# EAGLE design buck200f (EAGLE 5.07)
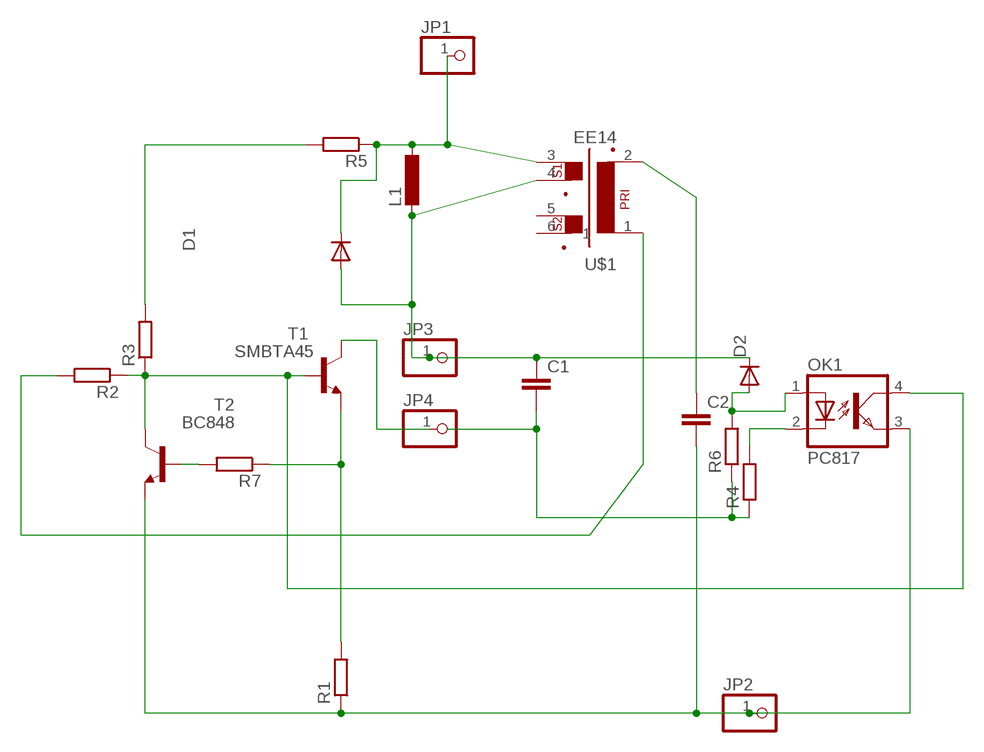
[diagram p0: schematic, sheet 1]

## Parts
C1  C-EU025-025X050  [C025-025X050]
C2  C-EUC0805  [C0805]
D1  DIODE-SMA-DO214  [SMA-DO214AC]
D2  DIODE-MINIMELF  [MINIMELF]
JP1  PINHD-1X11MM6  [1X1MM8]
JP2  PINHD-1X11MM6  [1X1MM8]
JP3  PINHD-1X11MM6  [1X1MM8]
JP4  PINHD-1X11MM6  [1X1MM8]
L1  L-EU0204/5  [0204/5]
OK1  PC817  [DIL04]
R1  R-EU_R0805  [R0805]
R2  R-EU_R0805  [R0805]
R3  R-EU_R1206  [R1206]
R4  R-EU_R0805  [R0805]
R5  R-EU_R1206  [R1206]
R6  R-EU_R0805  [R0805]
R7  R-EU_R0805  [R0805]
T1  SMBTA45  BC848  [SOT23]
T2  BC848  [SOT23]
U$1  EE14  [EE14]

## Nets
B1C2: OK1.4(COL) R2.1 R3.1 T1.B T2.C
C1: C1.1 D1.A D2.C JP3.1 L1.2 U$1.4
EB: R1.2 R7.1 T1.E
N$1: R3.2 R5.2
N$2: JP4.1 T1.C
N$3: R7.2 T2.B
N$4: R2.2 U$1.1
N$5: C1.2 R4.1 R6.1
N$6: C2.1 U$1.2
N$7: D2.A OK1.1(A) R6.2
N$8: OK1.2(C) R4.2
V+: D1.K(C) JP1.1 L1.1 R5.1 U$1.3
V-: C2.2 JP2.1 OK1.3(EMIT) R1.1 T2.E
Unconnected: U$1.5 U$1.6

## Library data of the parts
C1 C2 = rcl:C-EU: CAPACITOR, European symbol
D1 D2 = diode:DIODE-: DIODE
JP1-JP4 = pinhead:PINHD-1X1: PIN HEADER
L1 = rcl:L-EU: INDUCTOR, European symbol
OK1 = optocoupler:PC817: SHARP OPTO COUPLER
R1-R7 = rcl:R-EU_: RESISTOR, European symbol
T1 T2 = transistor:BC848: NPN TRANSISTOR
U$1 = trafo:EE14

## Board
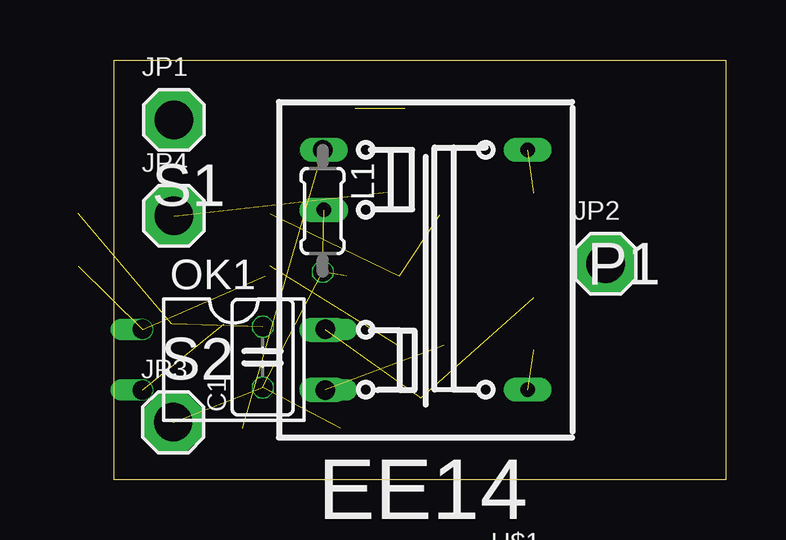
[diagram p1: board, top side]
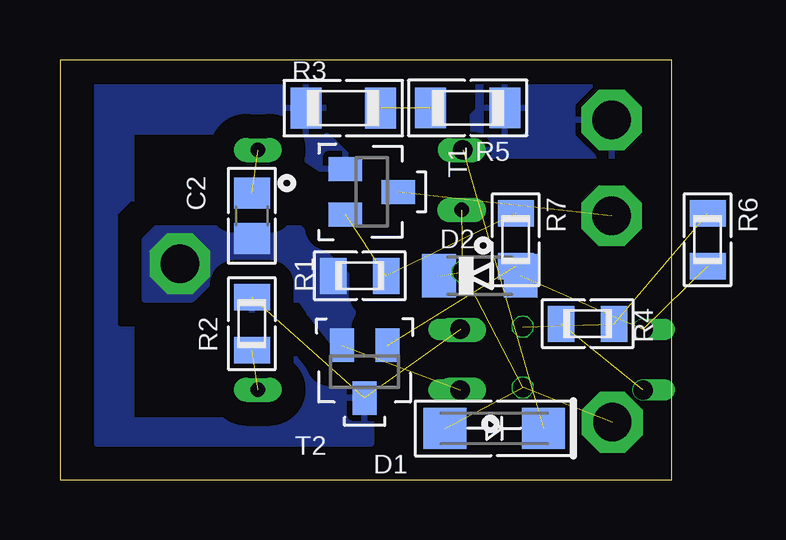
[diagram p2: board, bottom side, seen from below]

Size 25.5 x 17.5 mm. Coordinates in mm from the lower left corner, seen from the top.
Outline: 0,17.5 25.5,17.5 25.5,0 0,0 0,17.5
Copper layers (1*16): Top 0.035mm / dielectric 1.5mm / Bottom 0.035mm
Design rules "default": minimum track width 10mil, minimum drill 20mil, track to track 8mil, track to pad 8mil, pad to pad 8mil, via to via 8mil, smd to smd 8mil, copper to edge 40mil, drill to drill 8mil, minimum pad ring 1mil, minimum via ring 8mil, stop-mask expansion 4mil, vias tented up to drill 0mil, thermal gap 10mil

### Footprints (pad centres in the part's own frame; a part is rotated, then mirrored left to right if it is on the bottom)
C025-025X050 = drill 0.813 octagon: 1 -1.27,0; 2 1.27,0
C0805 = smd 1.3 x 1.5: 1 -0.95,0; 2 0.95,0
SMA-DO214AC = smd 1.8 x 1.7: A 2.05,-0.127; K -2.05,-0.127
MINIMELF = smd 1.4 x 1.8: A 1.7,0; C -1.7,0
1X1MM8 = drill 1.6 pad 2.54 octagon: 1 0,0
0204/5 = drill 0.813 octagon: 1 -2.54,0; 2 2.54,0
DIL04 = drill 0.813 offset: 1 -1.27,-3.81; 2 1.27,-3.81; 3 1.27,3.81; 4 -1.27,3.81
R0805 = smd 1.1 x 1.5: 1 -1.1,0; 2 1.1,0
R1206 = smd 1.3 x 1.7: 1 -1.55,0; 2 1.55,0
SOT23 = smd 1 x 1.4: B -0.95,-1.1; C 0,1.1; E 0.95,-1.1
EE14 = drill 0.6 pad 1 long: 1 4.25,-5; 2 4.25,5; 3 -4.25,5 | drill 0.6 pad 1.016 long: 4 -4.25,2.5; 5 -4.25,-2.5; 6 -4.25,-5

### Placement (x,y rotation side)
C1  6.2,5.11 90 top
C2  17.5,11 270 bottom
D1  7.39,2.01 180 bottom
D2  8,8.5 0 bottom
JP1  2.5,15 0 top
JP2  20.5,9 0 top
JP3  2.47,2.39 0 top
JP4  2.5,11 0 top
L1  8.7,11.2 270 top
OK1  5,5 270 top
R1  13,8.5 0 bottom
R2  17.5,6.5 270 bottom
R3  13.69,15.49 0 bottom
R4  3.5,6.5 180 bottom
R5  8.5,15.5 180 bottom
R6  -1.5,10 270 bottom
R7  6.5,10 270 bottom
T1  12.5,12 270 bottom
T2  12.8,4.5 180 bottom
U$1  13,8.75 0 top

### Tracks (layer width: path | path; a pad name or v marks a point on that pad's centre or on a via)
B1C2  (2 unrouted)
  pour Bottom (isolate 1, rank 3): 14.5,16.5 24,16.5 24,1.5 12.5,1.5 12.5,4.5 14,4.5 15,5.5 15.5,7 18.5,7.5 18.5,2.5 22.5,2.5 22.5,14.5 17,14.5 14,12.5 13,13 14.5,14.5
C1  (5 unrouted)
EB  (2 unrouted)
N$1  (1 unrouted)
N$2  (1 unrouted)
N$3  (1 unrouted)
N$4  (1 unrouted)
N$5  (2 unrouted)
N$6  (1 unrouted)
N$7  (2 unrouted)
N$8  (1 unrouted)
V+  (1 unrouted)
  pour Bottom (isolate 1, rank 4): 3,16.5 6,16.5 8.1,16.4 8.1,15.4 9,14.5 9.5,13.5 2,13.5
V-  (1 unrouted)
  pour Bottom (isolate 1, rank 2, no thermals): 15.5,10.5 21.5,10.5 22,10 22,7.5 20,7.5 19,8.5 16,8.5 16,7.5 15.5,7.5 15.1,6.9 14,5.5 13.2,5.4 13.3,8.3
